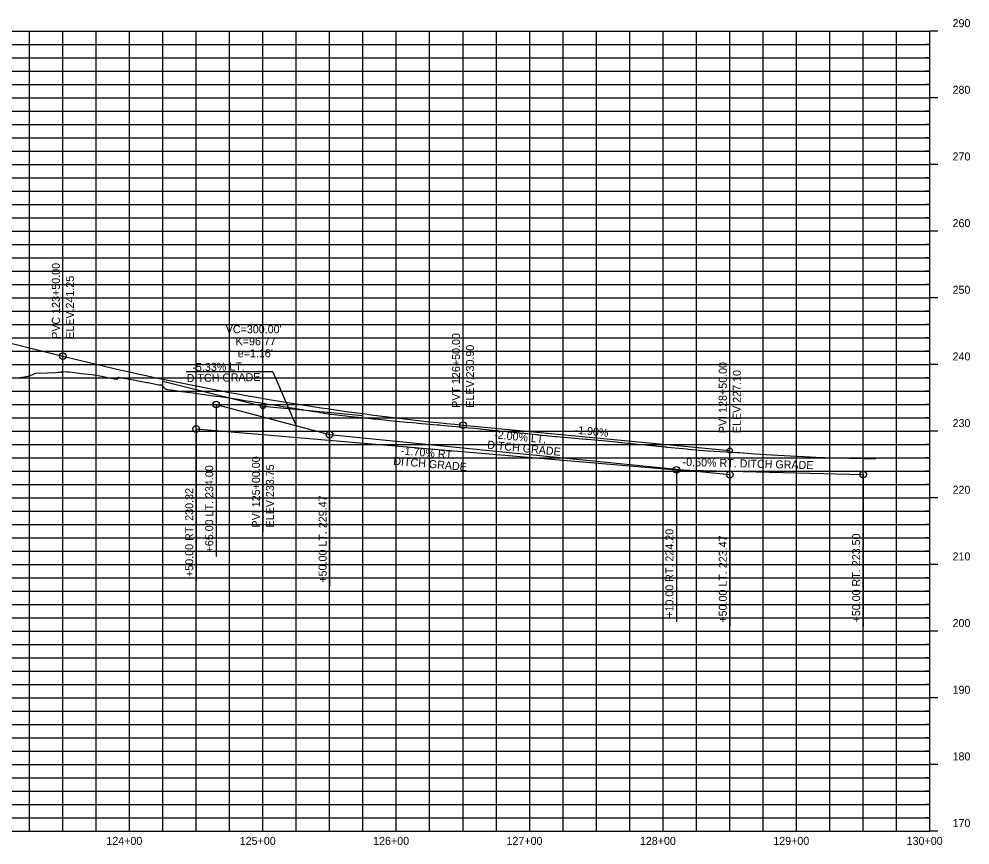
# Model space of a CAD drawing. Extents: x 921603 to 924670, y 1759276 to 1766491.
# Drawn here: x 923957 to 924670, y 1764922 to 1765541 of the extents above; entities that cross this region are included whole.
import ezdxf

# ---------------------------------------------------------------- set-up
doc = ezdxf.new("R2010")
doc.units = 0
for name, color, linetype in [('R_Axis_Annotation', 7, 'Continuous'), ('R_Exist Surface', 7, 'Continuous'), ('R_Grid', 7, 'Continuous'), ('R_Grid Annot', 7, 'Continuous'), ('R_Grid_Minor', 7, 'Continuous'), ('R_Vert Alg', 7, 'Continuous'), ('R_Vert Alg Annot', 7, 'Continuous')]:
    doc.layers.add(name, color=color, linetype=linetype)

msp = doc.modelspace()

# ---------------------------------------------------------------- linework, layer by layer
at = {"layer": 'R_Exist Surface'}
msp.add_lwpolyline([(923954.09, 1765271.97), (923961.01, 1765273.07), (923964.81, 1765273.66), (923969.34, 1765275.66), (923969.45, 1765275.67), (923977.89, 1765276), (923984.42, 1765276.26), (923986.33, 1765276.38), (923988.44, 1765276.51), (923989.16, 1765276.87), (923989.89, 1765277), (923992.82, 1765276.72), (923994.29, 1765276.73), (923994.76, 1765276.7), (923997, 1765276.54), (924001.94, 1765275.7), (924003.2, 1765275.57), (924011.64, 1765274.69), (924013.06, 1765274.54), (924015.06, 1765274.3), (924020.07, 1765273.27), (924027.42, 1765271.76), (924028.51, 1765271.56), (924029.48, 1765271.37), (924031.07, 1765271.11), (924031.34, 1765272.59), (924031.38, 1765272.73), (924031.82, 1765272.67), (924031.87, 1765272.7), (924035.23, 1765271.9), (924035.24, 1765271.89), (924035.24, 1765271.89), (924035.4, 1765271.87), (924036.95, 1765271.59), (924045.39, 1765270.11), (924052.68, 1765268.83), (924053.82, 1765268.6), (924061.66, 1765267.06), (924062.26, 1765267), (924063.57, 1765266.88), (924064.12, 1765266.82), (924066.32, 1765264.09), (924066.48, 1765263.85), (924067.64, 1765263.61), (924068.18, 1765263.49), (924068.23, 1765263.48), (924070.7, 1765263.16), (924079.13, 1765262.03), (924087.57, 1765260.89), (924090.56, 1765260.48), (924096.01, 1765259.72), (924104.45, 1765258.54), (924105.01, 1765258.46), (924109.39, 1765257.89), (924112.88, 1765257.37), (924119.16, 1765256.43), (924121.32, 1765256.09), (924126.47, 1765255.29), (924129.76, 1765254.78), (924138.19, 1765253.45), (924140.27, 1765253.13), (924143.78, 1765252.58), (924146.63, 1765252.12), (924155.07, 1765250.75), (924159.49, 1765250.04), (924163.51, 1765249.4), (924167.38, 1765248.78), (924171.94, 1765248.05), (924178.05, 1765247.07), (924180.38, 1765246.69), (924188.82, 1765245.31), (924190.66, 1765245.01), (924195.15, 1765244.46), (924197.25, 1765244.21), (924202.07, 1765243.63), (924205.69, 1765243.27), (924208.51, 1765242.98), (924214.13, 1765242.42), (924218.43, 1765241.99), (924222.57, 1765241.57), (924223.73, 1765241.45), (924231, 1765240.71), (924234.7, 1765240.33), (924237.75, 1765239.97), (924239.44, 1765239.82), (924247.88, 1765239.07), (924251.89, 1765238.72), (924254.65, 1765238.44), (924256.31, 1765238.29), (924264.75, 1765237.54), (924270.25, 1765237.05), (924272.22, 1765236.85), (924273.19, 1765236.76), (924281.63, 1765235.94), (924290.06, 1765235.12), (924291.97, 1765234.93), (924294.01, 1765234.8), (924298.5, 1765234.35), (924306.94, 1765233.5), (924314.48, 1765232.75), (924315.37, 1765232.69), (924315.86, 1765232.65), (924317.26, 1765232.53), (924337.9, 1765230.41), (924358.75, 1765228.26), (924359.94, 1765228.16), (924381.93, 1765226.23), (924383.12, 1765226.1), (924405.12, 1765224.16), (924406.3, 1765224.04), (924423.24, 1765222.32), (924424.24, 1765222.21), (924441.11, 1765220.49), (924442.19, 1765220.38), (924442.98, 1765220.32), (924457.63, 1765218.89), (924458.4, 1765218.83), (924473.08, 1765217.4), (924473.83, 1765217.34), (924495.41, 1765216.29), (924496.31, 1765216.21), (924497.18, 1765216.15), (924508.91, 1765215.32), (924521.16, 1765214.45), (924521.48, 1765214.43), (924539.89, 1765213.49), (924540.8, 1765213.44), (924558.78, 1765212.53), (924560.11, 1765212.46), (924561.46, 1765212.41), (924579.7, 1765211.9), (924580.98, 1765211.86), (924599.3, 1765211.35)], dxfattribs=at)
at = {"layer": 'R_Grid'}
for p, q in [((921639.83, 1765532.26), (924639.83, 1765532.26)), ((921639.83, 1765532.26), (924639.83, 1765532.26)), ((924039.83, 1764932.26), (924039.83, 1765532.26)), ((924139.83, 1764932.26), (924139.83, 1765532.26)), ((924239.83, 1764932.26), (924239.83, 1765532.26)), ((924339.83, 1764932.26), (924339.83, 1765532.26)), ((924439.83, 1764932.26), (924439.83, 1765532.26)), ((924539.83, 1764932.26), (924539.83, 1765532.26)), ((924639.83, 1764932.26), (924639.83, 1765532.26)), ((921639.83, 1765482.26), (924639.83, 1765482.26)), ((921639.83, 1765432.26), (924639.83, 1765432.26)), ((921639.83, 1765382.26), (924639.83, 1765382.26)), ((921639.83, 1765332.26), (924639.83, 1765332.26)), ((921639.83, 1765282.26), (924639.83, 1765282.26)), ((921639.83, 1765232.26), (924639.83, 1765232.26)), ((921639.83, 1765182.26), (924639.83, 1765182.26)), ((921639.83, 1765132.26), (924639.83, 1765132.26)), ((921639.83, 1765082.26), (924639.83, 1765082.26)), ((921639.83, 1765032.26), (924639.83, 1765032.26)), ((921639.83, 1764982.26), (924639.83, 1764982.26)), ((921639.83, 1764932.26), (924639.83, 1764932.26))]:
    msp.add_line(p, q, dxfattribs=at)
at = {"layer": 'R_Grid Annot'}
for p, q in [((924645.83, 1765532.26), (924639.83, 1765532.26)), ((924645.83, 1765532.26), (924639.83, 1765532.26)), ((924639.83, 1765522.26), (924636.83, 1765522.26)), ((924639.83, 1765512.26), (924636.83, 1765512.26)), ((924639.83, 1765502.26), (924636.83, 1765502.26)), ((924639.83, 1765492.26), (924636.83, 1765492.26)), ((924645.83, 1765482.26), (924639.83, 1765482.26)), ((924639.83, 1765472.26), (924636.83, 1765472.26)), ((924639.83, 1765462.26), (924636.83, 1765462.26)), ((924639.83, 1765452.26), (924636.83, 1765452.26)), ((924639.83, 1765442.26), (924636.83, 1765442.26)), ((924645.83, 1765432.26), (924639.83, 1765432.26)), ((924639.83, 1765422.26), (924636.83, 1765422.26)), ((924639.83, 1765412.26), (924636.83, 1765412.26)), ((924639.83, 1765402.26), (924636.83, 1765402.26)), ((924639.83, 1765392.26), (924636.83, 1765392.26)), ((924645.83, 1765382.26), (924639.83, 1765382.26)), ((924639.83, 1765372.26), (924636.83, 1765372.26)), ((924639.83, 1765362.26), (924636.83, 1765362.26)), ((924639.83, 1765352.26), (924636.83, 1765352.26)), ((924639.83, 1765342.26), (924636.83, 1765342.26)), ((924645.83, 1765332.26), (924639.83, 1765332.26)), ((924639.83, 1765322.26), (924636.83, 1765322.26)), ((924639.83, 1765312.26), (924636.83, 1765312.26)), ((924639.83, 1765302.26), (924636.83, 1765302.26)), ((924639.83, 1765292.26), (924636.83, 1765292.26)), ((924645.83, 1765282.26), (924639.83, 1765282.26)), ((924639.83, 1765272.26), (924636.83, 1765272.26)), ((924639.83, 1765262.26), (924636.83, 1765262.26)), ((924639.83, 1765252.26), (924636.83, 1765252.26)), ((924639.83, 1765242.26), (924636.83, 1765242.26)), ((924645.83, 1765232.26), (924639.83, 1765232.26)), ((924639.83, 1765222.26), (924636.83, 1765222.26)), ((924639.83, 1765212.26), (924636.83, 1765212.26)), ((924639.83, 1765202.26), (924636.83, 1765202.26)), ((924639.83, 1765192.26), (924636.83, 1765192.26)), ((924645.83, 1765182.26), (924639.83, 1765182.26)), ((924639.83, 1765172.26), (924636.83, 1765172.26)), ((924639.83, 1765162.26), (924636.83, 1765162.26)), ((924639.83, 1765152.26), (924636.83, 1765152.26)), ((924639.83, 1765142.26), (924636.83, 1765142.26)), ((924645.83, 1765132.26), (924639.83, 1765132.26)), ((924639.83, 1765122.26), (924636.83, 1765122.26)), ((924639.83, 1765112.26), (924636.83, 1765112.26)), ((924639.83, 1765102.26), (924636.83, 1765102.26)), ((924639.83, 1765092.26), (924636.83, 1765092.26)), ((924645.83, 1765082.26), (924639.83, 1765082.26)), ((924639.83, 1765072.26), (924636.83, 1765072.26)), ((924639.83, 1765062.26), (924636.83, 1765062.26)), ((924639.83, 1765052.26), (924636.83, 1765052.26)), ((924639.83, 1765042.26), (924636.83, 1765042.26)), ((924645.83, 1765032.26), (924639.83, 1765032.26)), ((924639.83, 1765022.26), (924636.83, 1765022.26)), ((924639.83, 1765012.26), (924636.83, 1765012.26)), ((924639.83, 1765002.26), (924636.83, 1765002.26)), ((924639.83, 1764992.26), (924636.83, 1764992.26)), ((924645.83, 1764982.26), (924639.83, 1764982.26)), ((924639.83, 1764972.26), (924636.83, 1764972.26)), ((924639.83, 1764962.26), (924636.83, 1764962.26)), ((924639.83, 1764952.26), (924636.83, 1764952.26)), ((924639.83, 1764942.26), (924636.83, 1764942.26)), ((924645.83, 1764932.26), (924639.83, 1764932.26))]:
    msp.add_line(p, q, dxfattribs=at)
at = {"layer": 'R_Grid_Minor'}
for p, q in [((923964.83, 1764932.26), (923964.83, 1765532.26)), ((923989.83, 1764932.26), (923989.83, 1765532.26)), ((924014.83, 1764932.26), (924014.83, 1765532.26)), ((924064.83, 1764932.26), (924064.83, 1765532.26)), ((924089.83, 1764932.26), (924089.83, 1765532.26)), ((924114.83, 1764932.26), (924114.83, 1765532.26)), ((924164.83, 1764932.26), (924164.83, 1765532.26)), ((924189.83, 1764932.26), (924189.83, 1765532.26)), ((924214.83, 1764932.26), (924214.83, 1765532.26)), ((924264.83, 1764932.26), (924264.83, 1765532.26)), ((924289.83, 1764932.26), (924289.83, 1765532.26)), ((924314.83, 1764932.26), (924314.83, 1765532.26)), ((924364.83, 1764932.26), (924364.83, 1765532.26)), ((924389.83, 1764932.26), (924389.83, 1765532.26)), ((924414.83, 1764932.26), (924414.83, 1765532.26)), ((924464.83, 1764932.26), (924464.83, 1765532.26)), ((924489.83, 1764932.26), (924489.83, 1765532.26)), ((924514.83, 1764932.26), (924514.83, 1765532.26)), ((924564.83, 1764932.26), (924564.83, 1765532.26)), ((924589.83, 1764932.26), (924589.83, 1765532.26)), ((924614.83, 1764932.26), (924614.83, 1765532.26)), ((921639.83, 1765522.26), (924639.83, 1765522.26)), ((921639.83, 1765512.26), (924639.83, 1765512.26)), ((921639.83, 1765502.26), (924639.83, 1765502.26)), ((921639.83, 1765492.26), (924639.83, 1765492.26)), ((921639.83, 1765472.26), (924639.83, 1765472.26)), ((921639.83, 1765462.26), (924639.83, 1765462.26)), ((921639.83, 1765452.26), (924639.83, 1765452.26)), ((921639.83, 1765442.26), (924639.83, 1765442.26)), ((921639.83, 1765422.26), (924639.83, 1765422.26)), ((921639.83, 1765412.26), (924639.83, 1765412.26)), ((921639.83, 1765402.26), (924639.83, 1765402.26)), ((921639.83, 1765392.26), (924639.83, 1765392.26)), ((921639.83, 1765372.26), (924639.83, 1765372.26)), ((921639.83, 1765362.26), (924639.83, 1765362.26)), ((921639.83, 1765352.26), (924639.83, 1765352.26)), ((921639.83, 1765342.26), (924639.83, 1765342.26)), ((921639.83, 1765322.26), (924639.83, 1765322.26)), ((921639.83, 1765312.26), (924639.83, 1765312.26)), ((921639.83, 1765302.26), (924639.83, 1765302.26)), ((921639.83, 1765292.26), (924639.83, 1765292.26)), ((921639.83, 1765272.26), (924639.83, 1765272.26)), ((921639.83, 1765262.26), (924639.83, 1765262.26)), ((921639.83, 1765252.26), (924639.83, 1765252.26)), ((921639.83, 1765242.26), (924639.83, 1765242.26)), ((921639.83, 1765222.26), (924639.83, 1765222.26)), ((921639.83, 1765212.26), (924639.83, 1765212.26)), ((921639.83, 1765202.26), (924639.83, 1765202.26)), ((921639.83, 1765192.26), (924639.83, 1765192.26)), ((921639.83, 1765172.26), (924639.83, 1765172.26)), ((921639.83, 1765162.26), (924639.83, 1765162.26)), ((921639.83, 1765152.26), (924639.83, 1765152.26)), ((921639.83, 1765142.26), (924639.83, 1765142.26)), ((921639.83, 1765122.26), (924639.83, 1765122.26)), ((921639.83, 1765112.26), (924639.83, 1765112.26)), ((921639.83, 1765102.26), (924639.83, 1765102.26)), ((921639.83, 1765092.26), (924639.83, 1765092.26)), ((921639.83, 1765072.26), (924639.83, 1765072.26)), ((921639.83, 1765062.26), (924639.83, 1765062.26)), ((921639.83, 1765052.26), (924639.83, 1765052.26)), ((921639.83, 1765042.26), (924639.83, 1765042.26)), ((921639.83, 1765022.26), (924639.83, 1765022.26)), ((921639.83, 1765012.26), (924639.83, 1765012.26)), ((921639.83, 1765002.26), (924639.83, 1765002.26)), ((921639.83, 1764992.26), (924639.83, 1764992.26)), ((921639.83, 1764972.26), (924639.83, 1764972.26)), ((921639.83, 1764962.26), (924639.83, 1764962.26)), ((921639.83, 1764952.26), (924639.83, 1764952.26)), ((921639.83, 1764942.26), (924639.83, 1764942.26))]:
    msp.add_line(p, q, dxfattribs=at)
at = {"layer": 'R_Vert Alg'}
for p, q in [((923859.83, 1765321.01), (923989.83, 1765288.51)), ((924104.83, 1765252.26), (924189.83, 1765229.61)), ((924289.83, 1765236.76), (924489.83, 1765217.76)), ((924089.83, 1765233.86), (924449.83, 1765203.26)), ((924189.83, 1765229.61), (924489.83, 1765199.61)), ((924449.83, 1765203.26), (924589.83, 1765199.76))]:
    msp.add_line(p, q, dxfattribs=at)
msp.add_lwpolyline([(923989.83, 1765288.51), (923996.08, 1765286.96), (924002.33, 1765285.42), (924008.58, 1765283.91), (924014.83, 1765282.42), (924021.08, 1765280.95), (924027.33, 1765279.5), (924033.58, 1765278.07), (924039.83, 1765276.66), (924046.08, 1765275.26), (924052.33, 1765273.89), (924058.58, 1765272.54), (924064.83, 1765271.21), (924071.08, 1765269.9), (924077.33, 1765268.61), (924083.58, 1765267.34), (924089.83, 1765266.09), (924096.08, 1765264.86), (924102.33, 1765263.65), (924108.58, 1765262.46), (924114.83, 1765261.3), (924121.08, 1765260.15), (924127.33, 1765259.02), (924133.58, 1765257.91), (924146.08, 1765255.75), (924152.33, 1765254.71), (924158.58, 1765253.68), (924164.83, 1765252.67), (924171.08, 1765251.68), (924177.33, 1765250.72), (924183.58, 1765249.77), (924189.83, 1765248.84), (924196.08, 1765247.94), (924202.33, 1765247.05), (924208.58, 1765246.18), (924214.83, 1765245.34), (924221.08, 1765244.51), (924227.33, 1765243.71), (924233.58, 1765242.92), (924239.83, 1765242.16), (924246.08, 1765241.41), (924252.33, 1765240.69), (924258.58, 1765239.98), (924264.83, 1765239.3), (924271.08, 1765238.63), (924277.33, 1765237.99), (924283.58, 1765237.36), (924289.83, 1765236.76)], dxfattribs=at)
at = {"layer": 'R_Vert Alg Annot'}
for p, q in [((923989.83, 1765298.51), (923989.83, 1765382.51)), ((924289.83, 1765246.76), (924289.83, 1765330.76)), ((924489.83, 1765227.76), (924489.83, 1765311.76)), ((923989.83, 1765288.51), (923989.83, 1765298.51)), ((924147.26, 1765276.79), (924082.36, 1765276.65)), ((924147.26, 1765276.79), (924164.83, 1765236.27)), ((924064.83, 1765269.76), (924139.83, 1765251.01)), ((924104.83, 1765252.26), (924104.83, 1765222.26)), ((924139.83, 1765251.01), (924214.83, 1765243.88)), ((924139.83, 1765251.01), (924139.83, 1765241.01)), ((924289.83, 1765236.76), (924289.83, 1765246.76)), ((924139.83, 1765241.01), (924139.83, 1765157.01)), ((924089.83, 1765233.86), (924089.83, 1765203.86)), ((924189.83, 1765229.61), (924189.83, 1765199.61)), ((924189.83, 1765229.61), (924189.83, 1765199.61)), ((924104.83, 1765222.26), (924104.83, 1765138.26)), ((924489.83, 1765217.76), (924489.83, 1765227.76)), ((924089.83, 1765203.86), (924089.83, 1765119.86)), ((924449.83, 1765203.26), (924449.83, 1765173.26)), ((924449.83, 1765203.26), (924449.83, 1765173.26)), ((924589.83, 1765199.76), (924589.83, 1765169.76)), ((924189.83, 1765199.61), (924189.83, 1765115.61)), ((924189.83, 1765199.61), (924189.83, 1765115.61)), ((924489.83, 1765199.61), (924489.83, 1765169.61)), ((924449.83, 1765173.26), (924449.83, 1765089.26)), ((924449.83, 1765173.26), (924449.83, 1765089.26)), ((924489.83, 1765169.61), (924489.83, 1765085.61)), ((924589.83, 1765169.76), (924589.83, 1765085.76))]:
    msp.add_line(p, q, dxfattribs=at)
for centre, radius in [((923989.83, 1765288.51), 2.5), ((924104.83, 1765252.26), 2.5), ((924139.83, 1765251.01), 1.85), ((924089.83, 1765233.86), 2.5), ((924289.83, 1765236.76), 2.5), ((924189.83, 1765229.61), 2.5), ((924189.83, 1765229.61), 2.5), ((924489.83, 1765217.76), 1.85), ((924449.83, 1765203.26), 2.5), ((924449.83, 1765203.26), 2.5), ((924489.83, 1765199.61), 2.5), ((924589.83, 1765199.76), 2.5)]:
    msp.add_circle(centre, radius, dxfattribs=at)

# ---------------------------------------------------------------- texts
at = {"layer": 'R_Axis_Annotation'}
for s, p in [('290', (924656.84, 1765535.26)), ('290', (924656.84, 1765535.26)), ('280', (924656.84, 1765485.26)), ('270', (924656.84, 1765435.26)), ('260', (924656.84, 1765385.26)), ('250', (924656.84, 1765335.26)), ('240', (924656.84, 1765285.26)), ('230', (924656.84, 1765235.26)), ('220', (924656.84, 1765185.26)), ('210', (924656.84, 1765135.26)), ('200', (924656.84, 1765085.26)), ('190', (924656.84, 1765035.26)), ('180', (924656.84, 1764985.26)), ('170', (924656.84, 1764935.26)), ('124+00', (924022.42, 1764921.91)), ('125+00', (924122.42, 1764921.91)), ('126+00', (924222.42, 1764921.91)), ('127+00', (924322.42, 1764921.91)), ('128+00', (924422.42, 1764921.91)), ('129+00', (924522.42, 1764921.91)), ('130+00', (924622.42, 1764921.91))]:
    msp.add_text(s, height=6, dxfattribs=at).set_placement(p)
at = {"layer": 'R_Vert Alg Annot'}
for s, rotation, p in [('PVC 123+50.00', 90, (923987.58, 1765301.51)), ('ELEV.241.25', 90, (923998.08, 1765301.51)), ('PVT 126+50.00', 90, (924287.58, 1765249.76)), ('ELEV.230.90', 90, (924298.08, 1765249.76)), ('-5.33% LT. ', 0.87012, (924086.99, 1765277.2)), ('PVI 128+50.00', 90, (924487.58, 1765230.76)), ('DITCH GRADE', 0.87012, (924082.73, 1765269.01)), ('ELEV.227.10', 90, (924498.08, 1765230.76)), ('-1.90%', 354.57319, (924373.24, 1765230.34)), ('-2.00% LT. ', 354.28941, (924312.95, 1765226.86)), ('DITCH GRADE', 354.28941, (924307.78, 1765219.21)), ('-1.70% RT.', 355.14154, (924243.18, 1765214.69)), ('PVI 125+00.00', 90, (924137.58, 1765160.01)), ('ELEV.233.75', 90, (924148.08, 1765160.01)), (' DITCH GRADE', 355.14154, (924235.14, 1765207.22)), ('-0.50% RT. DITCH GRADE', 358.5679, (924454.42, 1765206.15)), ('+65.00 LT. 234.00', 90, (924102.58, 1765141.26)), ('+50.00 RT. 230.32', 90, (924087.58, 1765122.86)), ('+50.00 LT. 229.47', 90, (924187.58, 1765118.61)), ('+50.00 LT. 229.47', 90, (924187.58, 1765118.61)), ('+10.00 RT. 224.20', 90, (924447.58, 1765092.26)), ('+10.00 RT. 224.20', 90, (924447.58, 1765092.26)), ('+50.00 LT. 223.47', 90, (924487.58, 1765088.61)), ('+50.00 RT. 223.50', 90, (924587.58, 1765088.76))]:
    msp.add_text(s, height=6, rotation=rotation, dxfattribs=at).set_placement(p)
for s, p in [("VC=300.00'", (924111.93, 1765305.65)), ('K=96.77', (924119.35, 1765296.65)), ("e=1.16'", (924120.93, 1765287.65))]:
    msp.add_text(s, height=6, dxfattribs=at).set_placement(p)

doc.saveas('drawing.dxf')
